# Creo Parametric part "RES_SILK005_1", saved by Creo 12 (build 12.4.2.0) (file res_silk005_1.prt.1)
Units: Custom; MM, KILOGRAM, SECS

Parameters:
  PTC_WM_ITERATION = "0"
  PTC_WM_VERSION = "-.0"
  PTC_WM_LIFECYCLE_STATE = "In Work"
  PTC_WM_LIFECYCLE = "MO_CADDocument"
  PTC_WM_CREATED_BY = "Maximilian Roepper (Z0017RMS: MO)"
  PTC_WM_CREATED_ON = "18-Sep-26 11:36:42 AM"
  PTC_WM_MODIFIED_BY = "Maximilian Roepper (Z0017RMS: MO)"
  PTC_WM_MODIFIED_ON = "18-Sep-26 11:36:46 AM"
  PDMLINKNUMBER = "PDM000071455133"
  PTC_WM_NAME = "res_silk005_1.prt"
  PTC_WM_NUMBER = "PDM000071455133"

Other parameters: WEIGHT, WEIGHT_FACTOR, WEIGHT_ADD, _MASS_TEMP, _DIFF_TEMP, MC_ERRORS, SUPPLIER

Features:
  1. coordinate system
  2. datum plane "PRT_YZ"
  3. datum plane "PRT_XY"
  4. datum plane "PRT_XZ"
  5. coordinate system
  6. datum axis
  7. datum axis
  8. datum axis
  9. coordinate system
  10. imported feature

Other named items: PRT, SIEMENS_MO, DRW_VIEW_ORG, PRT_X, PRT_Y, PRT_Z, CS0, ROUGH_GROB

Layers: 00_STD_CSYS-KSYS, 01_STD_PLANES-EBENEN, 02_STD_AXES-ACHSEN, 03_STD_CSYS-KSYS, 24_IMPORT_FEAT-IMPORT_KE

Surfaces: 10 plane, 8 cylinder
